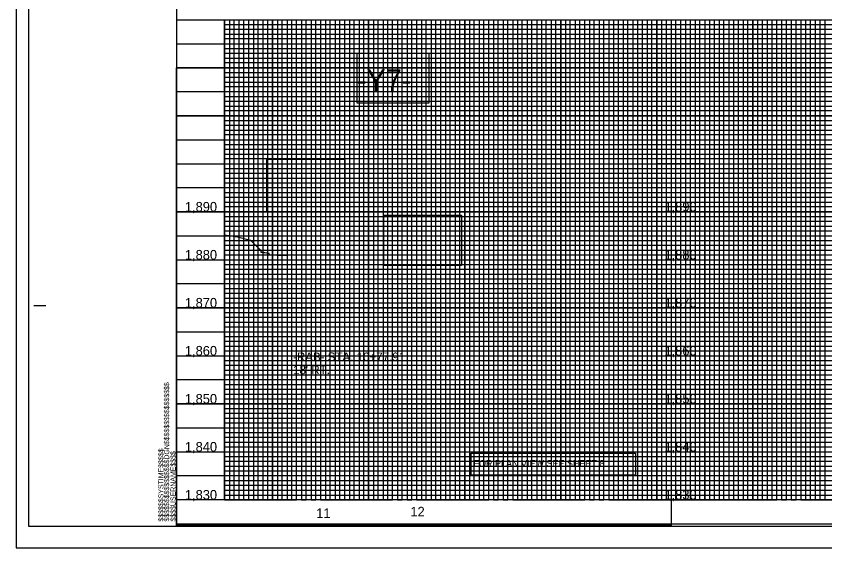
# Model space of a CAD drawing. Extents: x 557032 to 558716, y 525869 to 526969.
# Drawn here: x 557032 to 557874, y 525869 to 526423 of the extents above; entities that cross this region are included whole.
import ezdxf

# ---------------------------------------------------------------- set-up
doc = ezdxf.new("R2010")
doc.units = 0
for name, color, linetype in [('Exist Vertical Profile Horizontal Axis Label Major', 7, 'Continuous'), ('Exist Vertical Profile Vertical Axis Label', 7, 'Continuous'), ('Old_Level_63', 7, 'Continuous'), ('Prop Vertical Profile Curve Label', 7, 'Continuous'), ('Prop Vertical Profile Grade Label', 7, 'Continuous'), ('Prop VPI Label', 7, 'Continuous'), ('Scratch_Level_1', 7, 'Continuous'), ('Scratch_Level_5', 7, 'Continuous'), ('Sheet Cutting Line CELL', 7, 'Continuous'), ('Sheet DOT Grid CELL', 7, 'Continuous'), ('Sheet Layout Profile Border Port 2', 7, 'Continuous'), ('Sheet Plot Border Inside CELL', 7, 'Continuous'), ('Sheet Plot Border Outside CELL', 7, 'Continuous'), ('Sheet Profile CELL', 7, 'Continuous'), ('Sheet Profile Grid Major CELL', 7, 'Continuous'), ('Sheet Profile Grid Middle CELL', 7, 'Continuous'), ('Sheet Profile Grid Minor CELL', 7, 'Continuous')]:
    doc.layers.add(name, color=color, linetype=linetype)

msp = doc.modelspace()

# ---------------------------------------------------------------- linework, layer by layer
at = {"layer": 'Old_Level_63'}
msp.add_lwpolyline([(557699.45, 526269.22), (557749.45, 526269.22), (557749.45, 525919.22), (557699.45, 525919.22)], close=True, dxfattribs=at)
at = {"layer": 'Prop Vertical Profile Curve Label'}
for points in [[(557387.46, 526384.34), (557462.22, 526384.34), (557462.22, 526332.39), (557387.46, 526332.39)], [(557387.46, 526384.34), (557462.22, 526384.34), (557462.22, 526332.39), (557387.46, 526332.39)], [(557293.37, 526274.2), (557374.61, 526274.2), (557374.61, 526219.13), (557293.37, 526219.13)], [(557415.22, 526215.68), (557496.09, 526215.68), (557496.09, 526163.39), (557415.22, 526163.39)]]:
    msp.add_lwpolyline(points, close=True, dxfattribs=at)
at = {"layer": 'Prop VPI Label'}
for points in [[(557387.46, 526384.34), (557462.22, 526384.34), (557462.22, 526332.39), (557387.46, 526332.39)], [(557506.24, 525967.95), (557677.38, 525967.95), (557677.38, 525945.04), (557506.24, 525945.04)], [(557506.24, 525967.95), (557677.38, 525967.95), (557677.38, 525945.04), (557506.24, 525945.04)]]:
    msp.add_lwpolyline(points, close=True, dxfattribs=at)
at = {"layer": 'Scratch_Level_1'}
msp.add_lwpolyline([(557249.45, 526194.94), (557251.62, 526195.05), (557263, 526193.1), (557276.61, 526189.75), (557285.63, 526180.74), (557286.6, 526179.75), (557287.1, 526179.75), (557287.1, 526177.25), (557289.1, 526177.04), (557289.48, 526176.99), (557291.3, 526176.8), (557293.09, 526176.62), (557295.1, 526176.41), (557295.86, 526175.15), (557295.86, 526174.32), (557296.61, 526174.31), (557297.43, 526174.3), (557298.45, 526174.29), (557300.23, 526174.26), (557302.02, 526174.23), (557303.81, 526174.2), (557305.59, 526174.17), (557307.38, 526174.14), (557309.17, 526174.1), (557310.36, 526174.07), (557310.95, 526174.06), (557312.74, 526174.02), (557314.63, 526173.98)], dxfattribs=at)
at = {"layer": 'Scratch_Level_5'}
msp.add_lwpolyline([(557199.45, 526369.22), (557714.45, 526369.22), (557714.5, 525892.63), (557199.5, 525892.63)], close=True, dxfattribs=at)
at = {"layer": 'Sheet Cutting Line CELL'}
for p, q in [((557032.45, 526969.22), (557032.45, 525869.22)), ((557032.45, 525869.22), (558716.45, 525869.22))]:
    msp.add_line(p, q, dxfattribs=at)
at = {"layer": 'Sheet DOT Grid CELL'}
for p, q in [((557199.45, 526419.22), (558699.34, 526419.22)), ((557249.45, 526419.22), (557249.45, 525919.22)), ((557299.45, 526419.22), (557299.45, 525919.22)), ((557349.45, 526419.22), (557349.45, 525919.22)), ((557399.45, 526419.22), (557399.45, 525919.22)), ((557449.45, 526419.22), (557449.45, 525919.22)), ((557499.45, 526419.22), (557499.45, 525919.22)), ((557549.45, 526419.22), (557549.45, 525919.22)), ((557599.45, 526419.22), (557599.45, 525919.22)), ((557649.45, 526419.22), (557649.45, 525919.22)), ((557699.45, 526419.22), (557699.45, 525919.22)), ((557749.45, 526419.22), (557749.45, 525919.22)), ((557799.45, 526419.22), (557799.45, 525919.22)), ((557849.45, 526419.22), (557849.45, 525919.22)), ((557199.45, 526369.22), (558699.34, 526369.22)), ((557199.45, 526319.22), (558699.34, 526319.22)), ((557199.45, 526269.22), (558699.34, 526269.22)), ((557199.45, 526219.22), (558699.34, 526219.22)), ((557199.45, 526169.22), (558699.34, 526169.22)), ((557199.45, 526119.22), (558699.34, 526119.22)), ((557199.45, 526069.22), (558699.34, 526069.22)), ((557199.45, 526019.22), (558699.34, 526019.22)), ((557199.45, 525969.22), (558699.34, 525969.22))]:
    msp.add_line(p, q, dxfattribs=at)
at = {"layer": 'Sheet Layout Profile Border Port 2'}
msp.add_lwpolyline([(557249.45, 526419.22), (558649.45, 526419.22), (558649.45, 525919.22), (557249.45, 525919.22)], close=True, dxfattribs=at)
at = {"layer": 'Sheet Plot Border Inside CELL'}
msp.add_lwpolyline([(557045.45, 525891.67), (558711.95, 525891.67), (558711.95, 526946.77), (557045.45, 526946.77)], close=True, dxfattribs=at)
at = {"layer": 'Sheet Plot Border Outside CELL'}
msp.add_lwpolyline([(557032.45, 525869.22), (558716.45, 525869.22), (558716.45, 526969.22), (557032.45, 526969.22)], close=True, dxfattribs=at)
at = {"layer": 'Sheet Profile CELL'}
for p, q in [((557199.45, 526419.22), (558699.45, 526419.22)), ((557050.95, 526121.72), (557063.45, 526121.72)), ((558699.45, 525919.22), (557199.45, 525919.22)), ((557199.45, 525894.22), (558699.45, 525894.22)), ((557199.45, 525894.22), (557199.45, 525894.22)), ((557199.45, 525894.22), (557199.45, 525894.22)), ((557199.45, 525894.22), (557199.45, 525894.22)), ((557199.45, 525894.22), (557199.45, 525894.22)), ((557199.45, 525894.22), (557199.45, 525894.22)), ((557199.45, 525894.22), (557199.45, 525894.22)), ((557199.45, 525894.22), (557199.45, 525894.22))]:
    msp.add_line(p, q, dxfattribs=at)
msp.add_lwpolyline([(558699.45, 526944.22), (557199.45, 526944.22), (557199.45, 525894.22), (558699.45, 525894.22)], close=True, dxfattribs=at)
msp.add_lwpolyline([(557236.95, 525894.22), (557236.95, 525894.22)], dxfattribs=at)
at = {"layer": 'Sheet Profile Grid Major CELL'}
for p, q in [((557699.45, 526419.22), (557749.45, 526419.22)), ((557799.45, 526419.22), (557849.45, 526419.22)), ((557699.45, 526219.22), (557749.45, 526219.22)), ((557699.45, 526169.22), (557749.45, 526169.22)), ((557699.45, 526119.22), (557749.45, 526119.22)), ((557699.45, 526069.22), (557749.45, 526069.22)), ((557699.45, 526019.22), (557749.45, 526019.22)), ((557699.45, 525969.22), (557749.45, 525969.22)), ((557199.45, 525919.22), (557199.45, 525919.22))]:
    msp.add_line(p, q, dxfattribs=at)
for points in [[(557249.45, 526419.22), (557249.45, 525919.22), (557299.45, 525919.22), (557299.45, 526419.22), (557349.45, 526419.22), (557349.45, 525919.22), (557399.45, 525919.22), (557399.45, 526419.22), (557449.45, 526419.22), (557449.45, 525919.22), (557499.45, 525919.22), (557499.45, 526419.22), (557549.45, 526419.22), (557549.45, 525919.22), (557599.45, 525919.22), (557599.45, 526419.22), (557649.45, 526419.22), (557649.45, 525919.22), (557699.45, 525919.22), (557699.45, 526419.22), (557749.45, 526419.22), (557749.45, 525919.22), (557799.45, 525919.22), (557799.45, 526419.22), (557849.45, 526419.22), (557849.45, 525919.22), (557899.45, 525919.22)], [(558699.45, 526369.22), (557199.45, 526369.22)], [(558699.45, 526319.22), (557199.45, 526319.22), (557199.45, 526269.22), (558699.45, 526269.22)], [(558699.45, 526219.22), (557199.45, 526219.22), (557199.45, 526169.22), (558699.45, 526169.22)], [(558699.45, 526119.22), (557199.45, 526119.22), (557199.45, 526069.22), (558699.45, 526069.22)], [(558699.45, 526019.22), (557199.45, 526019.22), (557199.45, 526019.22), (557199.45, 525969.22), (558699.45, 525969.22)], [(558699.45, 525919.22), (557199.45, 525919.22)]]:
    msp.add_lwpolyline(points, dxfattribs=at)
msp.add_lwpolyline([(557699.45, 525919.22), (557749.45, 525919.22), (557749.45, 526269.22), (557699.45, 526269.22)], close=True, dxfattribs=at)
at = {"layer": 'Sheet Profile Grid Middle CELL'}
for points in [[(557224.45, 526419.22), (557274.45, 526419.22), (557274.45, 525919.22), (557324.45, 525919.22), (557324.45, 526419.22), (557374.45, 526419.22), (557374.45, 525919.22), (557424.45, 525919.22), (557424.45, 526419.22), (557474.45, 526419.22), (557474.45, 525919.22), (557524.45, 525919.22), (557524.45, 526419.22), (557574.45, 526419.22), (557574.45, 525919.22), (557624.45, 525919.22), (557624.45, 526419.22), (557674.45, 526419.22), (557674.45, 525919.22), (557724.45, 525919.22), (557724.45, 526419.22), (557774.45, 526419.22), (557774.45, 525919.22), (557824.45, 525919.22), (557824.45, 525919.22), (557824.45, 526419.22), (557874.45, 526419.22), (557874.45, 525919.22), (557924.45, 525919.22)], [(557199.45, 526394.22), (558699.45, 526394.22)], [(558699.45, 526344.22), (557199.45, 526344.22), (557199.45, 526294.22), (558699.45, 526294.22)], [(558699.45, 526244.22), (557199.45, 526244.22), (557199.45, 526194.22), (558699.45, 526194.22)], [(558699.45, 526144.22), (557199.45, 526144.22), (557199.45, 526094.22), (558699.45, 526094.22)], [(558546.09, 526044.22), (557199.45, 526044.22), (557199.45, 525994.22), (558699.45, 525994.22)], [(558699.45, 525944.22), (557199.45, 525944.22)]]:
    msp.add_lwpolyline(points, dxfattribs=at)
at = {"layer": 'Sheet Profile Grid Minor CELL'}
for p, q in [((557249.45, 526419.22), (557254.45, 526419.22)), ((557254.45, 526419.22), (557254.45, 525919.22)), ((557259.45, 525919.22), (557259.45, 526419.22)), ((557259.45, 526419.22), (557264.45, 526419.22)), ((557264.45, 526419.22), (557264.45, 525919.22)), ((557269.45, 525919.22), (557269.45, 526419.22)), ((557269.45, 526419.22), (557279.45, 526419.22)), ((557279.45, 526419.22), (557279.45, 525919.22)), ((557284.45, 525919.22), (557284.45, 526419.22)), ((557284.45, 526419.22), (557289.45, 526419.22)), ((557289.45, 526419.22), (557289.45, 525919.22)), ((557309.45, 525919.22), (557309.45, 526419.22)), ((557309.45, 526419.22), (557314.45, 526419.22)), ((557314.45, 526419.22), (557314.45, 525919.22)), ((557319.45, 525919.22), (557319.45, 526419.22)), ((557319.45, 526419.22), (557329.45, 526419.22)), ((557329.45, 526419.22), (557329.45, 525919.22)), ((557334.45, 525919.22), (557334.45, 526419.22)), ((557334.45, 526419.22), (557339.45, 526419.22)), ((557339.45, 526419.22), (557339.45, 525919.22)), ((557344.45, 525919.22), (557344.45, 526419.22)), ((557344.45, 526419.22), (557354.45, 526419.22)), ((557354.45, 526419.22), (557354.45, 525919.22)), ((557359.45, 525919.22), (557359.45, 526419.22)), ((557359.45, 526419.22), (557364.45, 526419.22)), ((557364.45, 526419.22), (557364.45, 525919.22)), ((557369.45, 525919.22), (557369.45, 526419.22)), ((557369.45, 526419.22), (557379.45, 526419.22)), ((557379.45, 526419.22), (557379.45, 525919.22)), ((557384.45, 525919.22), (557384.45, 526419.22)), ((557384.45, 526419.22), (557389.45, 526419.22)), ((557389.45, 526419.22), (557389.45, 525919.22)), ((557394.45, 525919.22), (557394.45, 526419.22)), ((557394.45, 526419.22), (557404.45, 526419.22)), ((557404.45, 526419.22), (557404.45, 525919.22)), ((557409.45, 525919.22), (557409.45, 526419.22)), ((557409.45, 526419.22), (557414.45, 526419.22)), ((557414.45, 526419.22), (557414.45, 525919.22)), ((557419.45, 525919.22), (557419.45, 526419.22)), ((557419.45, 526419.22), (557429.45, 526419.22)), ((557429.45, 526419.22), (557429.45, 525919.22)), ((557434.45, 525919.22), (557434.45, 526419.22)), ((557434.45, 526419.22), (557439.45, 526419.22)), ((557439.45, 526419.22), (557439.45, 525919.22)), ((557444.45, 525919.22), (557444.45, 526419.22)), ((557444.45, 526419.22), (557454.45, 526419.22)), ((557454.45, 526419.22), (557454.45, 525919.22)), ((557459.45, 525919.22), (557459.45, 526419.22)), ((557459.45, 526419.22), (557464.45, 526419.22)), ((557464.45, 526419.22), (557464.45, 525919.22)), ((557249.45, 526414.22), (558649.45, 526414.22)), ((558649.45, 526409.22), (557249.45, 526409.22)), ((557249.45, 526404.22), (558649.45, 526404.22)), ((558649.45, 526399.22), (557249.45, 526399.22)), ((557249.45, 526389.22), (558649.45, 526389.22)), ((558649.45, 526384.22), (557249.45, 526384.22)), ((557249.45, 526379.22), (558649.45, 526379.22)), ((558649.45, 526374.22), (557249.45, 526374.22)), ((557249.45, 526364.22), (558649.45, 526364.22)), ((558649.45, 526359.22), (557249.45, 526359.22)), ((557249.45, 526354.22), (558649.45, 526354.22)), ((558649.45, 526349.22), (557249.45, 526349.22)), ((557249.45, 526339.22), (558649.45, 526339.22)), ((558649.45, 526334.22), (557249.45, 526334.22)), ((557249.45, 526329.22), (558649.45, 526329.22)), ((558649.45, 526324.22), (557249.45, 526324.22)), ((557249.45, 526314.22), (558649.45, 526314.22)), ((558649.45, 526309.22), (557249.45, 526309.22)), ((557249.45, 526304.22), (558649.45, 526304.22)), ((558649.45, 526299.22), (557249.45, 526299.22)), ((557249.45, 526289.22), (558649.45, 526289.22)), ((558649.45, 526284.22), (557249.45, 526284.22)), ((557249.45, 526279.22), (558649.45, 526279.22)), ((558649.45, 526274.22), (557249.45, 526274.22)), ((557249.45, 526264.22), (558649.45, 526264.22)), ((558649.45, 526259.22), (557249.45, 526259.22)), ((557249.45, 526254.22), (558649.45, 526254.22)), ((558649.45, 526249.22), (557249.45, 526249.22)), ((557249.45, 526239.22), (558649.45, 526239.22)), ((558649.45, 526234.22), (557249.45, 526234.22)), ((557249.45, 526229.22), (558649.45, 526229.22)), ((558649.45, 526224.22), (557249.45, 526224.37)), ((557249.45, 526214.22), (558649.45, 526214.22)), ((558649.45, 526209.22), (557249.45, 526209.22)), ((557249.45, 526204.22), (558649.45, 526204.22)), ((558649.45, 526199.22), (557249.45, 526199.22)), ((557249.45, 526189.22), (558649.45, 526189.22)), ((558649.45, 526184.22), (557249.45, 526184.22)), ((557249.45, 526179.22), (558649.45, 526179.22)), ((558649.45, 526174.22), (557249.45, 526174.22)), ((557249.45, 526164.22), (558649.45, 526164.22)), ((558649.45, 526159.22), (557249.45, 526159.22)), ((557249.45, 526154.22), (558649.45, 526154.22)), ((558649.45, 526149.22), (557249.45, 526149.22)), ((557249.45, 526139.22), (558649.45, 526139.22)), ((558649.45, 526134.22), (557249.45, 526134.22)), ((557249.45, 526129.22), (558649.45, 526129.22)), ((558649.45, 526124.22), (557249.45, 526124.22)), ((557249.45, 526114.22), (558649.45, 526114.22)), ((558649.45, 526109.22), (557249.45, 526109.22)), ((557249.45, 526104.22), (558649.45, 526104.22)), ((558649.45, 526099.22), (557249.45, 526099.22)), ((557249.45, 526089.22), (558649.45, 526089.22)), ((558649.45, 526084.22), (557249.45, 526084.22)), ((557249.45, 526079.22), (558649.45, 526079.22)), ((558649.45, 526074.22), (557249.45, 526074.22)), ((557249.45, 526064.22), (558649.45, 526064.22)), ((558649.45, 526059.22), (557249.45, 526059.22)), ((557249.45, 526054.22), (558649.45, 526054.22)), ((558649.45, 526049.22), (557249.45, 526049.22)), ((557249.45, 526039.22), (558546.09, 526039.22)), ((558546.09, 526034.22), (557249.45, 526034.22)), ((557249.45, 526029.22), (558546.09, 526029.22)), ((558546.09, 526024.22), (557249.45, 526024.22)), ((557249.45, 526014.22), (558649.45, 526014.22)), ((558649.45, 526009.22), (557249.45, 526009.22)), ((557249.45, 526004.22), (558649.45, 526004.22)), ((558649.45, 525999.22), (557249.45, 525999.22)), ((557249.45, 525989.22), (558649.45, 525989.22)), ((558649.45, 525984.22), (557249.45, 525984.22)), ((557249.45, 525979.22), (558649.45, 525979.22)), ((558649.45, 525974.22), (557249.45, 525974.22)), ((557249.45, 525964.22), (558649.45, 525964.22)), ((558649.45, 525959.22), (557249.45, 525959.22)), ((557249.45, 525954.22), (558649.45, 525954.22)), ((558649.45, 525949.22), (557249.45, 525949.22)), ((557249.45, 525939.22), (558649.45, 525939.22)), ((558649.45, 525934.22), (557249.45, 525934.22)), ((557249.45, 525929.22), (558649.45, 525929.22)), ((557249.45, 525924.22), (558649.45, 525924.22)), ((557254.45, 525919.22), (557259.45, 525919.22)), ((557264.45, 525919.22), (557269.45, 525919.22)), ((557279.45, 525919.22), (557284.45, 525919.22)), ((557289.45, 525919.22), (557294.45, 525919.22)), ((557294.45, 525919.22), (557304.45, 525919.22)), ((557304.45, 525919.22), (557309.45, 525919.22)), ((557314.45, 525919.22), (557319.45, 525919.22)), ((557329.45, 525919.22), (557334.45, 525919.22)), ((557339.45, 525919.22), (557344.45, 525919.22)), ((557354.45, 525919.22), (557359.45, 525919.22)), ((557364.45, 525919.22), (557369.45, 525919.22)), ((557379.45, 525919.22), (557384.45, 525919.22)), ((557389.45, 525919.22), (557394.45, 525919.22)), ((557404.45, 525919.22), (557409.45, 525919.22)), ((557414.45, 525919.22), (557419.45, 525919.22)), ((557429.45, 525919.22), (557434.45, 525919.22)), ((557439.45, 525919.22), (557444.45, 525919.22)), ((557454.45, 525919.22), (557459.45, 525919.22))]:
    msp.add_line(p, q, dxfattribs=at)
for points in [[(557294.45, 525919.22), (557294.45, 526419.22), (557304.45, 526419.22), (557304.45, 525919.22)], [(557464.45, 525919.22), (557469.45, 525919.22), (557469.45, 526419.22), (557479.45, 526419.22), (557479.45, 525919.22), (557484.45, 525919.22), (557484.45, 526419.22), (557489.45, 526419.22), (557489.45, 525919.22), (557494.45, 525919.22), (557494.45, 526419.22), (557504.45, 526419.22), (557504.45, 525919.22), (557509.45, 525919.22), (557509.45, 526419.22), (557514.45, 526419.22), (557514.45, 525919.22), (557519.45, 525919.22), (557519.45, 526419.22), (557529.45, 526419.22), (557529.45, 525919.22), (557534.45, 525919.22), (557534.45, 526419.22), (557539.45, 526419.22), (557539.45, 525919.22), (557544.45, 525919.22), (557544.45, 526419.22), (557554.45, 526419.22), (557554.45, 525919.22), (557559.45, 525919.22), (557559.45, 526419.22), (557564.45, 526419.22), (557564.45, 525919.22), (557569.45, 525919.22), (557569.45, 526419.22), (557579.45, 526419.22), (557579.45, 525919.22), (557584.45, 525919.22), (557584.45, 526419.22), (557589.45, 526419.22), (557589.45, 525919.22), (557594.45, 525919.22), (557594.45, 526419.22), (557604.45, 526419.22), (557604.45, 525919.22), (557609.45, 525919.22), (557609.45, 526419.22), (557614.45, 526419.22), (557614.45, 525919.22), (557619.45, 525919.22), (557619.45, 526419.22), (557629.45, 526419.22), (557629.45, 525919.22), (557634.45, 525919.22), (557634.45, 526419.22), (557639.45, 526419.22), (557639.45, 525919.22), (557644.45, 525919.22), (557644.45, 526419.22), (557654.45, 526419.22), (557654.45, 525919.22), (557659.45, 525919.22), (557659.45, 526419.22), (557664.45, 526419.22), (557664.45, 525919.22), (557669.45, 525919.22), (557669.45, 526419.22), (557679.45, 526419.22), (557679.45, 525919.22), (557684.45, 525919.22), (557684.45, 526419.22), (557689.45, 526419.22), (557689.45, 525919.22), (557694.45, 525919.22), (557694.45, 526419.22), (557704.45, 526419.22), (557704.45, 525919.22), (557709.45, 525919.22), (557709.45, 526419.22), (557714.45, 526419.22), (557714.45, 525919.22), (557719.45, 525919.22), (557719.45, 526419.22), (557729.45, 526419.22), (557729.45, 525919.22), (557734.45, 525919.22), (557734.45, 526419.22), (557739.45, 526419.22), (557739.45, 525919.22), (557744.45, 525919.22), (557744.45, 526419.22), (557754.45, 526419.22), (557754.45, 525919.22), (557759.45, 525919.22), (557759.45, 526419.22), (557764.45, 526419.22), (557764.45, 525919.22), (557769.45, 525919.22), (557769.45, 526419.22), (557779.45, 526419.22)], [(557779.45, 526419.22), (557779.45, 525919.22), (557784.45, 525919.22), (557784.45, 526419.22), (557789.45, 526419.22), (557789.45, 525919.22), (557794.45, 525919.22), (557794.45, 526419.22), (557804.45, 526419.22), (557804.45, 525919.22), (557809.45, 525919.22), (557809.45, 526419.22), (557814.45, 526419.22), (557814.45, 525919.22), (557819.45, 525919.22), (557819.45, 526419.22), (557829.45, 526419.22), (557829.45, 525919.22), (557834.45, 525919.22), (557834.45, 526419.22), (557839.45, 526419.22), (557839.45, 525919.22), (557844.45, 525919.22), (557844.45, 526419.22), (557854.45, 526419.22), (557854.45, 525919.22), (557859.45, 525919.22), (557859.45, 526419.22), (557864.45, 526419.22), (557864.45, 525919.22), (557869.45, 525919.22), (557869.45, 526419.22), (557879.45, 526419.22)]]:
    msp.add_lwpolyline(points, dxfattribs=at)

# ---------------------------------------------------------------- texts
at = {"layer": 'Exist Vertical Profile Horizontal Axis Label Major'}
for s, p in [('11', (557344.88, 525900.29)), ('12', (557442.94, 525901.89))]:
    msp.add_text(s, height=10, dxfattribs=at).set_placement(p)
at = {"layer": 'Exist Vertical Profile Vertical Axis Label'}
for s, p in [('1,890', (557208.15, 526219.47)), ('1,890', (557707.51, 526219.47)), ('1,880', (557208.15, 526169.47)), ('1,880', (557707.51, 526169.47)), ('1,870', (557208.15, 526119.47)), ('1,870', (557707.51, 526119.47)), ('1,860', (557208.15, 526069.47)), ('1,860', (557707.51, 526069.47)), ('1,850', (557208.15, 526019.47)), ('1,850', (557707.51, 526019.47)), ('1,840', (557208.15, 525969.47)), ('1,840', (557707.51, 525969.47)), ('1,830', (557208.15, 525919.47)), ('1,830', (557707.51, 525919.47))]:
    msp.add_text(s, height=10, dxfattribs=at).set_placement(p)
at = {"layer": 'Prop Vertical Profile Grade Label'}
msp.add_text('-Y7-', height=22.5, dxfattribs=at).set_placement((557387.16, 526345.2))
at = {"layer": 'Prop VPI Label'}
for s, height, p in [('-RAB- STA. 10+77.91', 9, (557320.75, 526063.64)), ("18' RT.", 9, (557320.75, 526050.14)), ('FOR PLAN VIEW SEE SHEET 8', 7, (557508.68, 525953.61))]:
    msp.add_text(s, height=height, dxfattribs=at).set_placement(p)
at = {"layer": 'Sheet Profile CELL'}
for s, p in [('$$$$$$$$$$$$$$$$DGN$$$$$$$$$$$$$$$$', (557191.82, 525896.6)), ('$$$$$$SYSTIME$$$$$', (557185.77, 525896.6)), ('$$$$USERNAME$$$$', (557198.39, 525896.61))]:
    msp.add_text(s, height=5.25, rotation=90, dxfattribs=at).set_placement(p)

doc.saveas('drawing.dxf')
